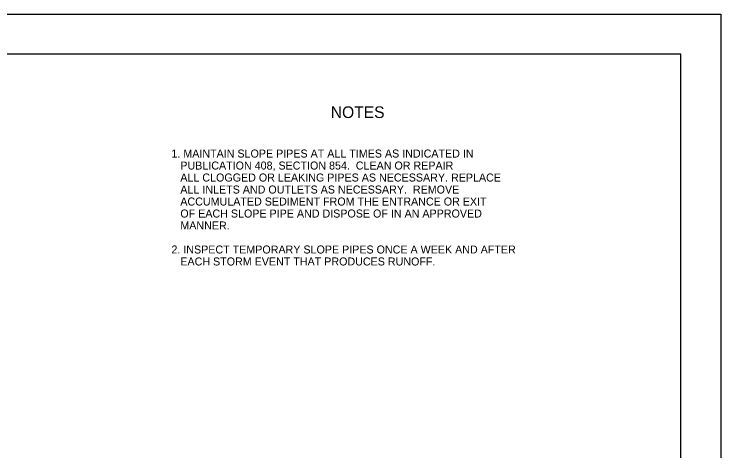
# Model space of a CAD drawing. Extents: x 636462 to 637367, y 299944 to 300538.
# Drawn here: x 637038.2 to 637302.9, y 300374.7 to 300538.4 of the extents above; entities that cross this region are included whole.
import ezdxf

# ---------------------------------------------------------------- set-up
doc = ezdxf.new("R2010")
doc.units = 0
for name, color, linetype in [('1', 7, 'Continuous'), ('Default', 7, 'Continuous'), ('PLT-BNDY', 7, 'Continuous')]:
    doc.layers.add(name, color=color, linetype=linetype)

msp = doc.modelspace()

# ---------------------------------------------------------------- linework, layer by layer
at = {"layer": '1'}
msp.add_lwpolyline([(637287.91, 299959.45), (637287.91, 300523.45), (636501.91, 300523.45), (636501.91, 299959.45), (637287.91, 299959.45), (637287.91, 299985.81), (637087.91, 299985.81), (637087.91, 300050.49), (637287.91, 300050.49), (637287.91, 300079.45), (637087.91, 300079.45), (637087.91, 299959.45), (637166.72, 299959.45), (637166.72, 299985.81), (637166.72, 299959.45), (637243.72, 299959.45), (637243.72, 299985.81), (637243.72, 299973.49), (637287.91, 299973.49)], dxfattribs=at)
at = {"layer": 'PLT-BNDY'}
msp.add_lwpolyline([(636461.91, 300538.45), (637302.91, 300538.45), (637302.91, 299944.45), (636461.91, 299944.45)], close=True, dxfattribs=at)

# ---------------------------------------------------------------- texts
at = {"layer": 'Default'}
for s, height, p in [('NOTES', 4.372, (637156.81, 300499.49)), ('1. MAINTAIN SLOPE PIPES AT ALL TIMES AS INDICATED IN', 2.998, (637097.11, 300484.67)), ('   PUBLICATION 408, SECTION 854.  CLEAN OR REPAIR', 2.998, (637097.11, 300480.17)), ('   ALL CLOGGED OR LEAKING PIPES AS NECESSARY. REPLACE', 2.998, (637097.11, 300475.68)), ('   ALL INLETS AND OUTLETS AS NECESSARY.  REMOVE', 2.998, (637097.11, 300471.18)), ('   ACCUMULATED SEDIMENT FROM THE ENTRANCE OR EXIT', 2.998, (637097.11, 300466.68)), ('   OF EACH SLOPE PIPE AND DISPOSE OF IN AN APPROVED', 2.998, (637097.11, 300462.18)), ('   MANNER.', 2.998, (637097.11, 300457.69)), ('2. INSPECT TEMPORARY SLOPE PIPES ONCE A WEEK AND AFTER', 2.998, (637097.11, 300448.69)), ('   EACH STORM EVENT THAT PRODUCES RUNOFF.', 2.998, (637097.11, 300444.2))]:
    msp.add_text(s, height=height, dxfattribs=at).set_placement(p)

doc.saveas('drawing.dxf')
